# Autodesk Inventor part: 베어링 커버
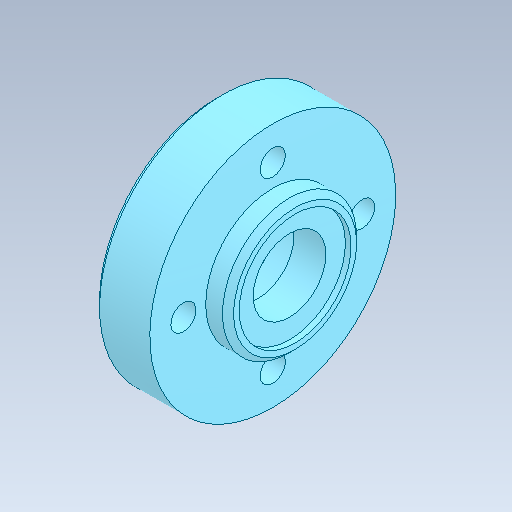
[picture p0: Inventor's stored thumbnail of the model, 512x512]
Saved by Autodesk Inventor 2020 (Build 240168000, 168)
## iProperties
Created: 2024-07
Part Number: 베어링 커버
Material: 강철, 연강
Document SubType Name: Modeling
Designer: oem
Density: 7.85 g/cm^3
Appearance: 기본값
Mass: 92.5315 g
Surface Area: 57.4361 cm^2
Volume: 11.7875 cm^3
Sending System: Autodesk Inventor 2025
Preprocessor: ST-DEVELOPER v20
Author: jhkim
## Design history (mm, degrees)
feature "솔리드1"
node "솔리드2"
